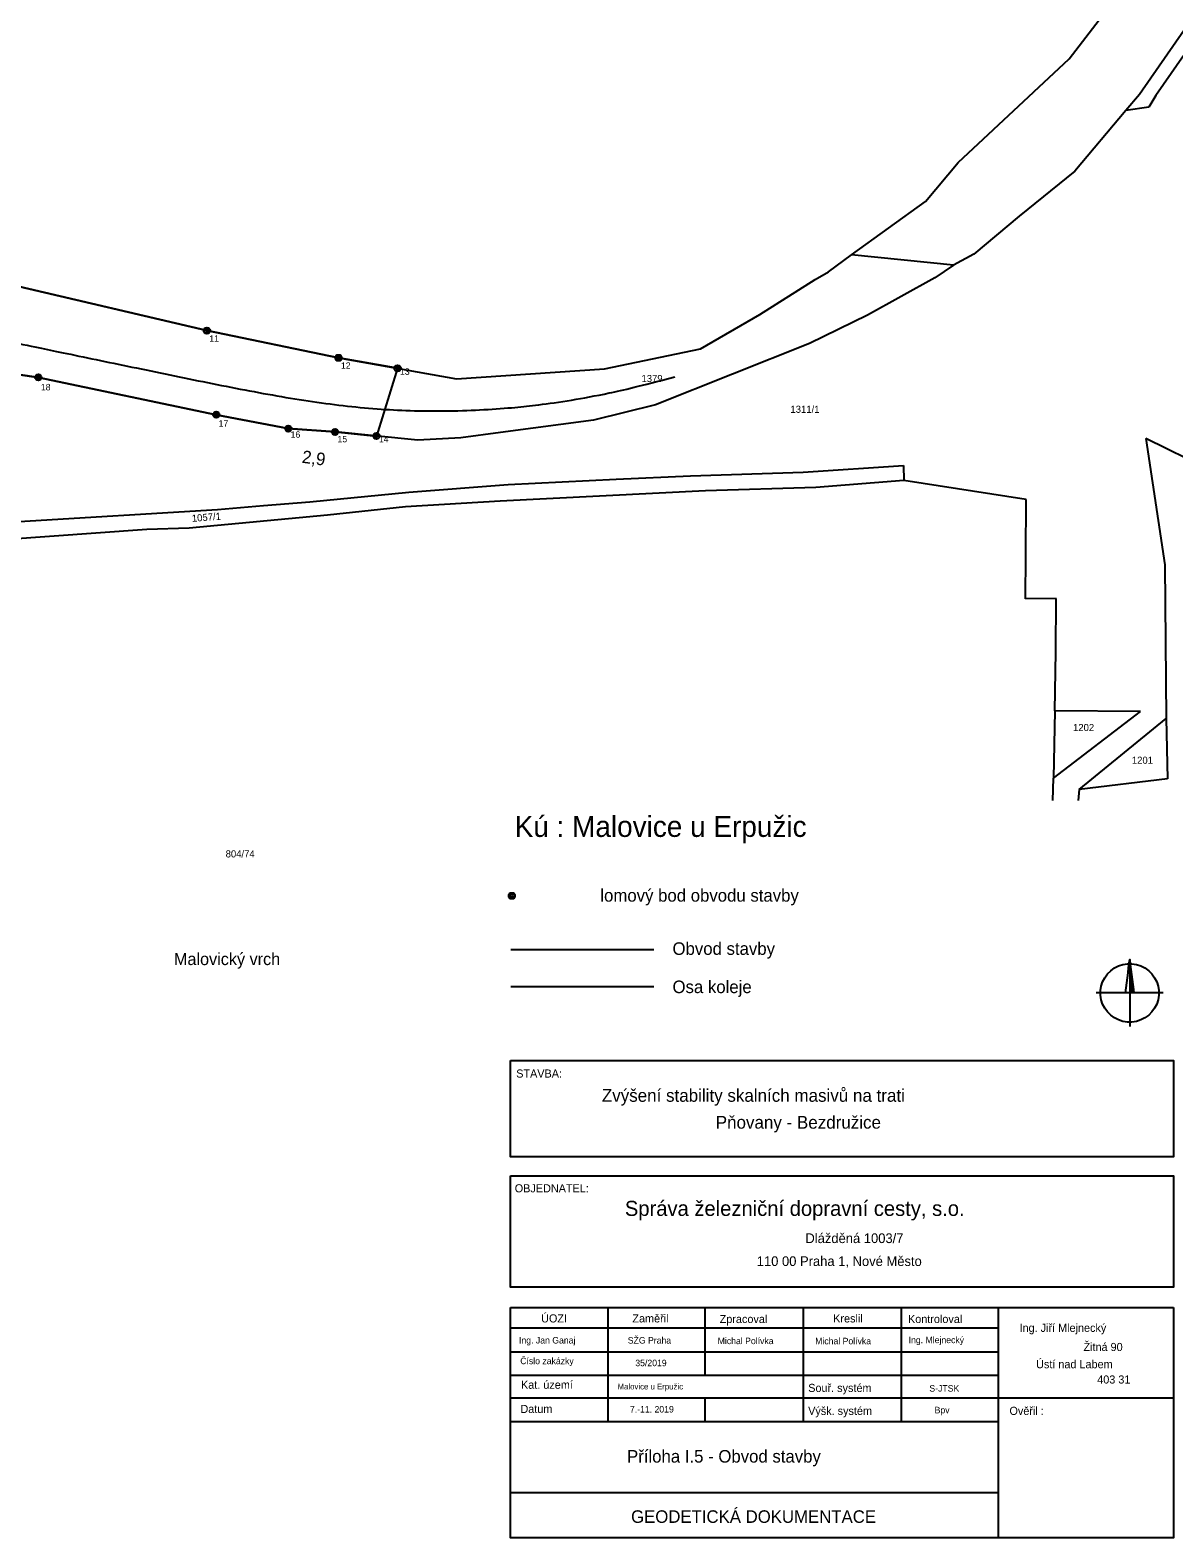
# Model space of a CAD drawing. Extents: x -852001 to -842497, y -1063614 to -1052182.
# Drawn here: x -843623.9 to -843350.2, y -1061566.6 to -1061205.9 of the extents above; entities that cross this region are included whole.
import ezdxf

# ---------------------------------------------------------------- set-up
doc = ezdxf.new("R2010")
doc.units = 0
for name, color, linetype in [('body', 7, 'Continuous'), ('cisla', 7, 'Continuous'), ('Default', 7, 'Continuous'), ('KN_HRANICE', 7, 'Continuous'), ('KN_PARCELY', 7, 'Continuous'), ('LEGENDA', 7, 'Continuous'), ('obvod_stavby', 7, 'Continuous'), ('tabulka', 7, 'Continuous'), ('Vrstva 7', 7, 'Continuous'), ('Železniční svršek', 7, 'Continuous')]:
    doc.layers.add(name, color=color, linetype=linetype)

# ---------------------------------------------------------------- blocks, each defined once
blk = doc.blocks.new('SEVER')
at = {"layer": 'Default'}
for points in [[(-10, 0), (-8.5, 12), (-7, 24), (-5.5, 36), (-4, 48), (-2.5, 60), (-1, 72), (0, 80), (1.5, 68), (3, 56), (4.5, 44), (6, 32), (7.5, 20), (9, 8), (10, 0), (9.2, 0.8), (9.2, 5.6), (8.4, 12), (8.4, 0.8), (7.6, 0.8), (7.6, 13.5), (7.6, 18.4), (6.8, 24.8), (6.8, 12.1), (6.8, 0.8), (6, 0.8), (6, 13.5), (6, 26.2), (6, 31.2), (5.2, 36.8), (5.2, 24.1), (5.2, 11.4), (5.2, 0.8), (4.4, 0.8), (4.4, 13.5), (4.4, 26.2), (4.4, 38.9), (4.4, 43.2), (3.6, 50.4), (3.6, 37.7), (3.6, 25), (3.6, 12.3), (3.6, 0.8), (2.8, 0.8), (2.8, 13.5), (2.8, 26.2), (2.8, 38.9), (2.8, 51.6), (2.8, 56), (2, 63.2), (2, 50.5), (2, 37.8), (2, 25.1), (2, 12.4), (2, 0.8), (1.2, 0.8), (1.2, 13.5), (1.2, 26.2), (1.2, 38.9), (1.2, 51.6), (1.2, 64.3), (1.2, 69.6), (0.4, 76), (0.4, 63.3), (0.4, 50.6), (0.4, 37.9), (0.4, 25.2), (0.4, 12.5), (0.4, 0.8)], [(0, 80), (0, 67.3), (0, 54.6), (0, 41.9), (0, 29.2), (0, 16.5), (0, 3.8), (0, -8.9), (0, -21.6), (0, -34.3), (0, -47), (0, -59.7), (0, -72.4), (0, -80)], [(5.5, 69.8), (16.3, 68.1), (26.7, 64.7), (36.5, 59.7), (45.4, 53.2), (53.2, 45.4), (59.7, 36.5), (64.7, 26.7), (68.1, 16.3), (69.8, 5.5), (69.8, -5.5), (68.1, -16.3), (64.7, -26.7), (59.7, -36.5), (53.2, -45.4), (45.4, -53.2), (36.5, -59.7), (26.7, -64.7), (16.3, -68.1), (5.5, -69.8), (-5.5, -69.8), (-16.3, -68.1), (-26.7, -64.7), (-36.5, -59.7), (-45.4, -53.2), (-53.2, -45.4), (-59.7, -36.5), (-64.7, -26.7), (-68.1, -16.3), (-69.8, -5.5), (-69.8, 5.5), (-68.1, 16.3), (-64.7, 26.7), (-59.7, 36.5), (-53.2, 45.4), (-45.4, 53.2), (-36.5, 59.7), (-26.7, 64.7), (-16.3, 68.1), (-5.5, 69.8), (5.5, 69.8)], [(80, 0), (67.3, 0), (54.6, 0), (41.9, 0), (29.2, 0), (16.5, 0), (3.8, 0), (-8.9, 0), (-21.6, 0), (-34.3, 0), (-47, 0), (-59.7, 0), (-72.4, 0), (-80, 0)]]:
    blk.add_lwpolyline(points, dxfattribs=at)

msp = doc.modelspace()

# ---------------------------------------------------------------- linework, layer by layer
at = {"layer": 'body'}
for p, q in [((-843581.64, -1061277.78), (-843581.64, -1061277.78)), ((-843550.13, -1061284.28), (-843550.13, -1061284.28)), ((-843536, -1061286.79), (-843536, -1061286.79)), ((-843621.95, -1061288.97), (-843621.95, -1061288.97)), ((-843579.4, -1061297.9), (-843579.4, -1061297.9)), ((-843562.17, -1061301.21), (-843562.17, -1061301.21)), ((-843550.96, -1061302.01), (-843550.96, -1061302.01)), ((-843541.06, -1061302.98), (-843541.06, -1061302.98))]:
    msp.add_line(p, q, dxfattribs=at)
for centre, radius in [((-843581.64, -1061277.78), 0.75), ((-843581.64, -1061277.78), 0.35), ((-843550.13, -1061284.28), 0.75), ((-843550.13, -1061284.28), 0.35), ((-843536.01, -1061286.79), 0.75), ((-843536.01, -1061286.79), 0.35), ((-843621.95, -1061288.97), 0.75), ((-843621.95, -1061288.97), 0.35), ((-843579.4, -1061297.9), 0.75), ((-843579.4, -1061297.9), 0.35), ((-843562.17, -1061301.21), 0.75), ((-843562.17, -1061301.21), 0.35), ((-843550.96, -1061302.01), 0.75), ((-843550.96, -1061302.01), 0.35), ((-843541.06, -1061302.98), 0.75), ((-843541.06, -1061302.98), 0.35), ((-843508.66, -1061413), 0.75), ((-843508.66, -1061413), 0.35)]:
    msp.add_circle(centre, radius, dxfattribs=at)
at = {"layer": 'KN_HRANICE'}
for p, q in [((-843375.27, -1061212.74), (-843364.89, -1061199.29)), ((-843375.27, -1061212.74), (-843364.89, -1061199.29)), ((-843347.73, -1061205.9), (-843358.48, -1061221.24)), ((-843347.73, -1061205.9), (-843358.48, -1061221.24)), ((-843345.94, -1061209.17), (-843354.51, -1061221.49)), ((-843345.94, -1061209.17), (-843354.51, -1061221.49)), ((-843401.81, -1061237.57), (-843375.27, -1061212.74)), ((-843401.81, -1061237.57), (-843375.27, -1061212.74)), ((-843358.48, -1061221.24), (-843361.73, -1061225.11)), ((-843358.48, -1061221.24), (-843361.73, -1061225.11)), ((-843354.51, -1061221.49), (-843356.26, -1061224.28)), ((-843354.51, -1061221.49), (-843356.26, -1061224.28)), ((-843361.73, -1061225.11), (-843373.92, -1061239.66)), ((-843361.73, -1061225.11), (-843373.92, -1061239.66)), ((-843356.26, -1061224.28), (-843361.73, -1061225.11)), ((-843356.26, -1061224.28), (-843361.73, -1061225.11)), ((-843409.66, -1061246.9), (-843401.81, -1061237.57)), ((-843409.66, -1061246.9), (-843401.81, -1061237.57)), ((-843373.92, -1061239.66), (-843387.27, -1061250.35)), ((-843373.92, -1061239.66), (-843387.27, -1061250.35)), ((-843427.39, -1061259.6), (-843409.66, -1061246.9)), ((-843427.39, -1061259.6), (-843409.66, -1061246.9)), ((-843387.27, -1061250.35), (-843398.13, -1061259.5)), ((-843387.27, -1061250.35), (-843398.13, -1061259.5)), ((-843432.88, -1061263.72), (-843427.39, -1061259.6)), ((-843432.88, -1061263.72), (-843427.39, -1061259.6)), ((-843402.94, -1061262.13), (-843427.39, -1061259.6)), ((-843402.94, -1061262.13), (-843427.39, -1061259.6)), ((-843402.94, -1061262.13), (-843407.4, -1061265.11)), ((-843402.94, -1061262.13), (-843407.4, -1061265.11)), ((-843398.13, -1061259.5), (-843402.94, -1061262.13)), ((-843398.13, -1061259.5), (-843402.94, -1061262.13)), ((-843449.35, -1061273.91), (-843436.08, -1061265.55)), ((-843449.35, -1061273.91), (-843436.08, -1061265.55)), ((-843436.08, -1061265.55), (-843432.88, -1061263.72)), ((-843436.08, -1061265.55), (-843432.88, -1061263.72)), ((-843407.4, -1061265.11), (-843423.53, -1061274.04)), ((-843407.4, -1061265.11), (-843423.53, -1061274.04)), ((-843627.97, -1061266.91), (-843581.64, -1061277.78)), ((-843627.97, -1061266.91), (-843581.64, -1061277.78)), ((-843463.49, -1061282.11), (-843449.35, -1061273.91)), ((-843463.49, -1061282.11), (-843449.35, -1061273.91)), ((-843423.53, -1061274.04), (-843437.44, -1061280.86)), ((-843423.53, -1061274.04), (-843437.44, -1061280.86)), ((-843581.64, -1061277.78), (-843550.13, -1061284.28)), ((-843581.64, -1061277.78), (-843550.13, -1061284.28)), ((-843486.48, -1061286.92), (-843463.49, -1061282.11)), ((-843486.48, -1061286.92), (-843463.49, -1061282.11)), ((-843437.44, -1061280.86), (-843474.28, -1061295.51)), ((-843437.44, -1061280.86), (-843474.28, -1061295.51)), ((-843621.95, -1061288.97), (-843654.49, -1061284.29)), ((-843621.95, -1061288.97), (-843654.49, -1061284.29)), ((-843550.13, -1061284.28), (-843521.88, -1061289.31)), ((-843550.13, -1061284.28), (-843521.88, -1061289.31)), ((-843521.88, -1061289.31), (-843486.48, -1061286.92)), ((-843521.88, -1061289.31), (-843486.48, -1061286.92)), ((-843579.4, -1061297.9), (-843621.95, -1061288.97)), ((-843579.4, -1061297.9), (-843621.95, -1061288.97)), ((-843562.17, -1061301.21), (-843579.4, -1061297.9)), ((-843562.17, -1061301.21), (-843579.4, -1061297.9)), ((-843474.28, -1061295.51), (-843489.15, -1061299.17)), ((-843474.28, -1061295.51), (-843489.15, -1061299.17)), ((-843550.96, -1061302.01), (-843562.17, -1061301.21)), ((-843550.96, -1061302.01), (-843562.17, -1061301.21)), ((-843531.17, -1061303.96), (-843550.96, -1061302.01)), ((-843531.17, -1061303.96), (-843550.96, -1061302.01)), ((-843489.15, -1061299.17), (-843511.38, -1061302.13)), ((-843489.15, -1061299.17), (-843511.38, -1061302.13)), ((-843520.88, -1061303.39), (-843531.17, -1061303.96)), ((-843520.88, -1061303.39), (-843531.17, -1061303.96)), ((-843511.38, -1061302.13), (-843520.88, -1061303.39)), ((-843511.38, -1061302.13), (-843520.88, -1061303.39)), ((-843336.05, -1061313.93), (-843356.91, -1061303.61)), ((-843356.91, -1061303.61), (-843352.41, -1061333.79)), ((-843336.05, -1061313.93), (-843356.91, -1061303.61)), ((-843356.91, -1061303.61), (-843352.41, -1061333.79)), ((-843483.68, -1061313.34), (-843465.9, -1061312.5)), ((-843483.68, -1061313.34), (-843465.9, -1061312.5)), ((-843465.9, -1061312.5), (-843438.96, -1061311.66)), ((-843465.9, -1061312.5), (-843438.96, -1061311.66)), ((-843438.96, -1061311.66), (-843414.92, -1061310.01)), ((-843438.96, -1061311.66), (-843414.92, -1061310.01)), ((-843414.92, -1061310.01), (-843414.84, -1061313.61)), ((-843414.92, -1061310.01), (-843414.84, -1061313.61)), ((-843556.99, -1061318.74), (-843533.28, -1061316.39)), ((-843556.99, -1061318.74), (-843533.28, -1061316.39)), ((-843533.28, -1061316.39), (-843509.52, -1061314.59)), ((-843533.28, -1061316.39), (-843509.52, -1061314.59)), ((-843462.31, -1061316.14), (-843511.44, -1061318.56)), ((-843462.31, -1061316.14), (-843511.44, -1061318.56)), ((-843509.52, -1061314.59), (-843483.68, -1061313.34)), ((-843509.52, -1061314.59), (-843483.68, -1061313.34)), ((-843435.93, -1061315.31), (-843462.31, -1061316.14)), ((-843435.93, -1061315.31), (-843462.31, -1061316.14)), ((-843414.84, -1061313.61), (-843435.93, -1061315.31)), ((-843414.84, -1061313.61), (-843435.93, -1061315.31)), ((-843385.55, -1061318.17), (-843414.84, -1061313.61)), ((-843385.55, -1061318.17), (-843414.84, -1061313.61)), ((-843579.08, -1061320.55), (-843568.11, -1061319.58)), ((-843579.08, -1061320.55), (-843568.11, -1061319.58)), ((-843568.11, -1061319.58), (-843556.99, -1061318.74)), ((-843568.11, -1061319.58), (-843556.99, -1061318.74)), ((-843534.11, -1061319.89), (-843552.81, -1061321.96)), ((-843534.11, -1061319.89), (-843552.81, -1061321.96)), ((-843511.44, -1061318.56), (-843534.11, -1061319.89)), ((-843511.44, -1061318.56), (-843534.11, -1061319.89)), ((-843385.63, -1061331.59), (-843385.55, -1061318.17)), ((-843385.63, -1061331.59), (-843385.55, -1061318.17)), ((-843626.56, -1061323.43), (-843579.08, -1061320.55)), ((-843626.56, -1061323.43), (-843579.08, -1061320.55)), ((-843552.81, -1061321.96), (-843585.86, -1061325.04)), ((-843552.81, -1061321.96), (-843585.86, -1061325.04)), ((-843596.03, -1061325.37), (-843630.42, -1061327.79)), ((-843596.03, -1061325.37), (-843630.42, -1061327.79)), ((-843585.86, -1061325.04), (-843596.03, -1061325.37)), ((-843585.86, -1061325.04), (-843596.03, -1061325.37)), ((-843385.72, -1061341.93), (-843385.63, -1061331.59)), ((-843385.72, -1061341.93), (-843385.63, -1061331.59)), ((-843352.41, -1061333.79), (-843352.08, -1061370.58)), ((-843352.41, -1061333.79), (-843352.08, -1061370.58)), ((-843378.38, -1061341.85), (-843385.72, -1061341.93)), ((-843378.38, -1061341.85), (-843385.72, -1061341.93)), ((-843378.47, -1061354.64), (-843378.38, -1061341.85)), ((-843378.47, -1061354.64), (-843378.38, -1061341.85)), ((-843378.72, -1061368.73), (-843378.47, -1061354.64)), ((-843378.72, -1061368.73), (-843378.47, -1061354.64)), ((-843378.72, -1061368.73), (-843379.05, -1061384.82)), ((-843378.72, -1061368.73), (-843379.05, -1061384.82)), ((-843379.05, -1061384.82), (-843358.22, -1061368.89)), ((-843379.05, -1061384.82), (-843358.22, -1061368.89)), ((-843358.22, -1061368.89), (-843378.72, -1061368.73)), ((-843358.22, -1061368.89), (-843378.72, -1061368.73)), ((-843372.91, -1061387.59), (-843352.08, -1061370.58)), ((-843372.91, -1061387.59), (-843352.08, -1061370.58)), ((-843352.08, -1061370.58), (-843351.74, -1061385)), ((-843352.08, -1061370.58), (-843351.74, -1061385)), ((-843379.18, -1061390.16), (-843379.05, -1061384.82)), ((-843379.18, -1061390.16), (-843379.05, -1061384.82)), ((-843351.74, -1061385), (-843372.91, -1061387.59)), ((-843351.74, -1061385), (-843372.91, -1061387.59)), ((-843372.91, -1061387.59), (-843373.16, -1061390.16)), ((-843372.91, -1061387.59), (-843373.16, -1061390.16))]:
    msp.add_line(p, q, dxfattribs=at)
at = {"layer": 'LEGENDA'}
for p, q in [((-843508.86, -1061425.86), (-843474.66, -1061425.86)), ((-843508.86, -1061434.69), (-843474.66, -1061434.69))]:
    msp.add_line(p, q, dxfattribs=at)
at = {"layer": 'obvod_stavby'}
msp.add_line((-843536.01, -1061286.79), (-843541.07, -1061302.99), dxfattribs=at)
for points in [[(-843536.01, -1061286.79), (-843550.13, -1061284.28), (-843581.64, -1061277.78), (-843627.97, -1061266.91), (-843651.14, -1061260.86), (-843707.71, -1061252.4), (-843719.38, -1061254.23), (-843749.69, -1061258.46), (-843763.99, -1061263.04), (-843785.22, -1061267.47), (-843789.91, -1061274.45), (-843803.41, -1061279.25)], [(-843804.96, -1061294.74), (-843791.76, -1061285.89), (-843787.23, -1061282.93), (-843782.31, -1061287.73), (-843772.02, -1061280.75), (-843753.6, -1061279.61), (-843720.66, -1061276.06), (-843701.61, -1061278.11), (-843689.83, -1061280.06), (-843654.49, -1061284.29), (-843621.95, -1061288.97), (-843579.4, -1061297.9), (-843562.17, -1061301.21), (-843550.96, -1061302.01), (-843541.07, -1061302.99)]]:
    msp.add_lwpolyline(points, dxfattribs=at)
at = {"layer": 'tabulka'}
for p, q in [((-843508.95, -1061511.47), (-843350.29, -1061511.47)), ((-843485.66, -1061511.47), (-843485.66, -1061538.78)), ((-843462.51, -1061511.47), (-843462.51, -1061527.67)), ((-843438.91, -1061511.47), (-843438.91, -1061538.78)), ((-843415.47, -1061511.47), (-843415.47, -1061538.78)), ((-843392.17, -1061566.6), (-843392.17, -1061511.47)), ((-843508.95, -1061516.37), (-843392.17, -1061516.37)), ((-843508.95, -1061522.09), (-843392.17, -1061522.09)), ((-843508.95, -1061527.67), (-843392.17, -1061527.67)), ((-843508.95, -1061533.08), (-843350.29, -1061533.08)), ((-843462.51, -1061533.08), (-843462.51, -1061538.78)), ((-843508.95, -1061538.78), (-843392.17, -1061538.78)), ((-843508.95, -1061555.78), (-843392.17, -1061555.78))]:
    msp.add_line(p, q, dxfattribs=at)
for points in [[(-843508.95, -1061452.38), (-843350.29, -1061452.38), (-843350.29, -1061475.44), (-843508.95, -1061475.44)], [(-843508.95, -1061479.96), (-843350.29, -1061479.96), (-843350.29, -1061506.65), (-843508.95, -1061506.65)]]:
    msp.add_lwpolyline(points, close=True, dxfattribs=at)
msp.add_lwpolyline([(-843350.29, -1061511.47), (-843350.29, -1061566.6), (-843508.95, -1061566.6), (-843508.95, -1061511.47)], dxfattribs=at)
at = {"layer": 'Železniční svršek'}
msp.add_open_spline([(-843814.8, -1061292.46), (-843807.55, -1061288.51), (-843800.05, -1061284.84), (-843795.59, -1061282.83), (-843792.03, -1061281.34), (-843784.97, -1061278.61), (-843777.74, -1061276.13), (-843769.61, -1061273.72), (-843761.54, -1061271.7), (-843752.93, -1061269.93), (-843744.31, -1061268.56), (-843737, -1061267.68), (-843731.14, -1061267.17), (-843722.35, -1061266.75), (-843713.28, -1061266.75), (-843703.86, -1061267.17), (-843695.99, -1061267.88), (-843686.54, -1061269.1), (-843677.48, -1061270.59), (-843668.34, -1061272.3), (-843659.18, -1061274.15), (-843650.24, -1061275.99), (-843640.69, -1061277.96), (-843631.28, -1061279.9), (-843622.03, -1061281.82), (-843617.49, -1061282.77), (-843609.21, -1061284.48), (-843600.78, -1061286.23), (-843591.65, -1061288.12), (-843582.54, -1061289.99), (-843573.66, -1061291.77), (-843564.83, -1061293.4), (-843556.32, -1061294.8), (-843547.97, -1061295.88), (-843539.88, -1061296.61), (-843532.11, -1061296.98), (-843523.63, -1061297.04), (-843515.26, -1061296.73), (-843507.43, -1061296.12), (-843502.84, -1061295.63), (-843494.35, -1061294.43), (-843485.91, -1061292.87), (-843478.02, -1061291.08), (-843469.68, -1061288.8)], degree=3, dxfattribs=at)

# ---------------------------------------------------------------- block references
at = {"layer": 'LEGENDA', "xscale": 0.1, "yscale": 0.10000000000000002}
msp.add_blockref('SEVER', (-843360.8, -1061436.23), dxfattribs=at)

# ---------------------------------------------------------------- texts
at = {"layer": 'cisla'}
for s, p in [(' 11', (-843581.64, -1061280.45)), (' 12', (-843550.13, -1061286.91)), (' 13', (-843536, -1061288.34)), (' 18', (-843621.95, -1061292.07)), (' 17', (-843579.4, -1061300.75)), (' 16', (-843562.17, -1061303.41)), (' 15', (-843550.96, -1061304.5)), (' 14', (-843541.06, -1061304.53))]:
    msp.add_text(s, height=1.552, dxfattribs=at).set_placement(p)
at = {"layer": 'KN_PARCELY'}
for s, height, p in [('1379', 1.7, (-843477.64, -1061290.08)), ('1379', 1.7, (-843477.64, -1061290.08)), ('1311/1', 1.7, (-843441.99, -1061297.44)), ('1311/1', 1.7, (-843441.99, -1061297.44)), ('1202', 1.7, (-843374.36, -1061373.57)), ('1202', 1.7, (-843374.36, -1061373.57)), ('1201', 1.7, (-843360.28, -1061381.4)), ('1201', 1.7, (-843360.28, -1061381.4)), ('804/74', 1.7, (-843577.15, -1061403.81)), ('804/74', 1.7, (-843577.15, -1061403.81)), ('Malovický vrch', 2.9, (-843589.52, -1061429.56)), ('Malovický vrch', 2.9, (-843589.52, -1061429.56))]:
    msp.add_text(s, height=height, dxfattribs=at).set_placement(p)
msp.add_text('1057/1', height=1.7, rotation=4.412, dxfattribs=at).set_placement((-843585.17, -1061323.54))
msp.add_text('1057/1', height=1.7, rotation=4.412, dxfattribs=at).set_placement((-843585.17, -1061323.54))
at = {"layer": 'LEGENDA'}
for s, height, p in [('Kú : Malovice u Erpužic', 5, (-843507.99, -1061398.9)), ('lomový bod obvodu stavby', 3, (-843487.48, -1061414.39)), ('Obvod stavby', 3, (-843470.21, -1061427.12)), ('Osa koleje', 3, (-843470.21, -1061436.27)), ('Zvýšení stability skalních masivů na trati', 3.04, (-843487.12, -1061462.27)), ('Pňovany - Bezdružice', 3.04, (-843459.86, -1061468.7))]:
    msp.add_text(s, height=height, dxfattribs=at).set_placement(p)
at = {"layer": 'tabulka'}
for s, height, p in [('STAVBA:', 1.94, (-843507.61, -1061456.48)), ('OBJEDNATEL:', 1.94, (-843507.96, -1061483.94)), ('Správa železniční dopravní cesty, s.o.', 3.61, (-843481.61, -1061489.58)), ('Dlážděná 1003/7', 2.32, (-843438.4, -1061496.07)), ('110 00 Praha 1, Nové Město', 2.32, (-843450.05, -1061501.56)), ('ÚOZI', 1.94, (-843501.65, -1061515.06)), ('Zaměřil', 1.94, (-843479.81, -1061515.06)), ('Zpracoval', 1.94, (-843458.92, -1061515.21)), ('Kreslil', 1.94, (-843431.76, -1061515.06)), ('Kontroloval', 1.94, (-843413.85, -1061515.21)), ('Ing. Jan Ganaj', 1.552, (-843506.94, -1061520.1)), ('SŽG Praha', 1.552, (-843480.92, -1061520.12)), ('Ing. Mlejnecký', 1.552, (-843413.7, -1061520.02)), ('Ing. Jiří Mlejnecký', 1.94, (-843387.16, -1061517.32)), ('Michal Polívka', 1.552, (-843459.4, -1061520.25)), ('Michal Polívka', 1.552, (-843436.07, -1061520.29)), ('Žitná 90', 1.94, (-843371.86, -1061521.9)), ('Číslo zakázky', 1.552, (-843506.65, -1061525.05)), ('35/2019', 1.552, (-843479.11, -1061525.53)), ('Ústí nad Labem', 1.94, (-843383.2, -1061526.02)), ('Kat. území', 1.94, (-843506.46, -1061530.93)), ('403 31', 1.94, (-843368.57, -1061529.68)), ('Malovice u Erpužic', 1.3968, (-843483.36, -1061531.09)), ('Souř. systém', 1.94, (-843437.73, -1061531.69)), ('S-JTSK', 1.552, (-843408.74, -1061531.61)), ('Datum', 1.94, (-843506.6, -1061536.72)), ('7.-11. 2019', 1.552, (-843480.4, -1061536.61)), ('Výšk. systém', 1.94, (-843437.75, -1061537.18)), ('Bpv', 1.552, (-843407.48, -1061536.79)), ('Ověřil :', 1.94, (-843389.57, -1061537.18)), ('Příloha I.5 - Obvod stavby', 3, (-843481.09, -1061548.59)), ('GEODETICKÁ DOKUMENTACE ', 3, (-843480.13, -1061563.01))]:
    msp.add_text(s, height=height, dxfattribs=at).set_placement(p)
at = {"layer": 'Vrstva 7'}
msp.add_text('2,9', height=3, rotation=352.5028, dxfattribs=at).set_placement((-843559.01, -1061309.37))

doc.saveas('drawing.dxf')
